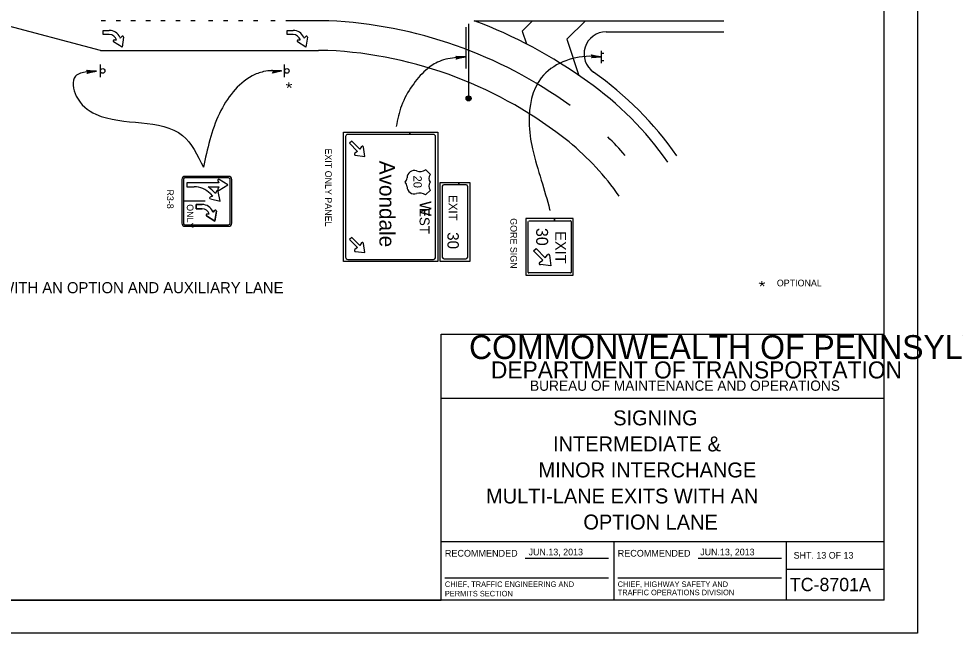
# Model space of a CAD drawing. Extents: x 644898 to 648326, y 298294 to 300670.
# Drawn here: x 645333.7 to 645756.3, y 298294.5 to 298571.8 of the extents above; entities that cross this region are included whole.
import ezdxf

# ---------------------------------------------------------------- set-up
doc = ezdxf.new("R2010")
doc.units = 0
for name, color, linetype in [('1', 7, 'Continuous'), ('2', 7, 'Continuous'), ('XCS-GRID-MIN', 7, 'Continuous')]:
    doc.layers.add(name, color=color, linetype=linetype)

msp = doc.modelspace()

# ---------------------------------------------------------------- linework, layer by layer
at = {"layer": '1'}
for p, q in [((645724.32, 298309.49), (645724.32, 298873.49)), ((645524.32, 298309.49), (645524.32, 298429.49)), ((645524.32, 298429.49), (645724.32, 298429.49)), ((645724.32, 298400.49), (645524.32, 298400.49)), ((645524.32, 298335.87), (645724.32, 298335.87)), ((645602.32, 298335.87), (645602.32, 298309.49)), ((645680.2, 298309.49), (645680.2, 298335.87)), ((645562.26, 298328.44), (645599.88, 298328.44)), ((645640.26, 298328.44), (645677.88, 298328.44)), ((645680.2, 298323.49), (645724.32, 298323.49)), ((645526.01, 298319.54), (645599.88, 298319.54)), ((645604.01, 298319.54), (645677.88, 298319.54)), ((645724.32, 298309.49), (644938.32, 298309.49)), ((644938.32, 298309.49), (645524.32, 298309.49))]:
    msp.add_line(p, q, dxfattribs=at)
at = {"layer": '2'}
for p, q in [((645370.54, 298557.51), (645319.78, 298570.89)), ((645372.84, 298570.89), (645370.84, 298570.89)), ((645379.59, 298570.89), (645377.59, 298570.89)), ((645386.34, 298570.89), (645384.34, 298570.89)), ((645393.09, 298570.89), (645391.09, 298570.89)), ((645399.84, 298570.89), (645397.84, 298570.89)), ((645406.59, 298570.89), (645404.59, 298570.89)), ((645413.34, 298570.89), (645411.34, 298570.89)), ((645421.34, 298570.89), (645419.34, 298570.89)), ((645428.09, 298570.89), (645426.09, 298570.89)), ((645434.84, 298570.89), (645432.84, 298570.89)), ((645441.59, 298570.89), (645439.59, 298570.89)), ((645449.45, 298570.89), (645447.45, 298570.89)), ((645473.61, 298570.89), (645454.2, 298570.89)), ((645539.18, 298570.89), (645598.81, 298570.89)), ((645565.62, 298570.89), (645560.93, 298566.2)), ((645589.44, 298570.89), (645581.09, 298562.54)), ((645598.81, 298570.89), (645651.96, 298570.89)), ((645535.6, 298549.4), (645535.6, 298567.99)), ((645536.72, 298569.47), (645536.72, 298535.78)), ((645560.93, 298566.2), (645562.85, 298560.41)), ((645598.81, 298565.89), (645651.96, 298565.89)), ((645581.09, 298562.54), (645586.5, 298546.22)), ((645370.54, 298557.51), (645442.59, 298557.51)), ((645442.59, 298557.51), (645454.2, 298557.51)), ((645454.2, 298557.51), (645468.92, 298557.51)), ((645596.63, 298551.75), (645596.63, 298557.38)), ((645596.63, 298556.25), (645597.75, 298556.25)), ((645370.54, 298545.44), (645370.54, 298551.07)), ((645453.63, 298545.44), (645453.63, 298551.07)), ((645596.63, 298552.88), (645597.75, 298552.88)), ((645537.22, 298536.53), (645535.97, 298536.16)), ((645536.1, 298536.53), (645537.22, 298536.53)), ((645537.22, 298535.03), (645536.6, 298536.78)), ((645536.6, 298536.78), (645537.72, 298535.66)), ((645537.72, 298535.66), (645537.22, 298536.66)), ((645537.47, 298536.03), (645535.85, 298535.66)), ((645536.6, 298535.03), (645535.85, 298535.91)), ((645535.85, 298535.91), (645537.22, 298535.03)), ((645535.85, 298535.66), (645537.72, 298535.66)), ((645535.97, 298536.16), (645537.47, 298536.03)), ((645537.72, 298535.66), (645535.97, 298535.28)), ((645535.97, 298535.28), (645537.47, 298535.28)), ((645537.47, 298535.28), (645536.6, 298535.03)), ((645536.72, 298535.78), (645536.72, 298535.78)), ((645480.21, 298462.22), (645480.21, 298520.6)), ((645480.21, 298520.6), (645510.23, 298520.6)), ((645510.23, 298519.6), (645510.23, 298520.6)), ((645510.23, 298520.6), (645522.83, 298520.6)), ((645510.23, 298520.6), (645510.23, 298519.6)), ((645522.83, 298520.6), (645522.83, 298462.22)), ((645481.21, 298518.6), (645481.21, 298464.22)), ((645483.94, 298516.57), (645482.94, 298515.57)), ((645482.94, 298515.57), (645486.56, 298511.95)), ((645487.56, 298512.89), (645483.94, 298516.57)), ((645521.83, 298464.22), (645521.83, 298518.6)), ((645486.56, 298511.95), (645485.37, 298511.07)), ((645488.37, 298514.07), (645487.56, 298512.89)), ((645489.81, 298509.7), (645489.31, 298513.82)), ((645485.56, 298510.2), (645489.81, 298509.7)), ((645517.21, 298503.76), (645519.46, 298501.51)), ((645423.55, 298498.77), (645423.94, 298497.79)), ((645428, 298496.85), (645424.21, 298499.31)), ((645508.96, 298500.01), (645508.96, 298500.01)), ((645423.94, 298497.79), (645409.55, 298497.79)), ((645409.55, 298497.79), (645409.55, 298495.95)), ((645409.55, 298495.95), (645412.85, 298495.95)), ((645419.14, 298495.92), (645423.94, 298495.92)), ((645422.42, 298492.96), (645421.35, 298494.1)), ((645423.94, 298495.92), (645423.55, 298494.94)), ((645424.21, 298494.39), (645428, 298496.85)), ((645508.96, 298496.01), (645508.96, 298496.01)), ((645511.46, 298495.76), (645511.46, 298495.76)), ((645513.71, 298498.01), (645513.71, 298498.01)), ((645513.71, 298498.01), (645513.71, 298498.01)), ((645513.71, 298498.01), (645513.71, 298498.01)), ((645513.71, 298498.01), (645513.71, 298498.01)), ((645513.71, 298498.01), (645513.71, 298498.01)), ((645513.71, 298498.01), (645513.71, 298498.01)), ((645519.46, 298494.38), (645517.21, 298492.26)), ((645523.83, 298462.22), (645523.83, 298497.85)), ((645523.83, 298497.85), (645532.29, 298497.85)), ((645524.83, 298496.22), (645524.83, 298464.1)), ((645532.29, 298496.85), (645525.58, 298496.85)), ((645532.29, 298496.85), (645532.29, 298497.85)), ((645532.29, 298497.85), (645537.33, 298497.85)), ((645532.29, 298497.85), (645532.29, 298496.85)), ((645535.58, 298496.85), (645532.29, 298496.85)), ((645536.33, 298464.1), (645536.33, 298496.22)), ((645537.33, 298497.85), (645537.33, 298462.22)), ((645420.04, 298492.86), (645421.11, 298491.72)), ((645421.11, 298491.72), (645420.1, 298491.32)), ((645420.16, 298490.47), (645424.55, 298489.4)), ((645422.88, 298493.95), (645422.42, 298492.96)), ((645424.55, 298489.4), (645423.73, 298493.85)), ((645512.21, 298492.76), (645512.21, 298492.76)), ((645575.53, 298481.6), (645562.57, 298481.6)), ((645562.57, 298481.6), (645562.57, 298456.08)), ((645575.53, 298480.6), (645575.53, 298481.6)), ((645583.95, 298481.6), (645575.53, 298481.6)), ((645575.53, 298481.6), (645575.53, 298480.6)), ((645583.95, 298456.08), (645583.95, 298481.6)), ((645563.57, 298457.33), (645563.57, 298480.35)), ((645563.82, 298480.6), (645575.53, 298480.6)), ((645575.53, 298480.6), (645582.7, 298480.6)), ((645582.95, 298480.35), (645582.95, 298457.33)), ((645483.94, 298473.12), (645482.94, 298472.12)), ((645487.56, 298469.43), (645483.94, 298473.12)), ((645482.94, 298472.12), (645486.56, 298468.5)), ((645488.37, 298470.62), (645487.56, 298469.43)), ((645489.81, 298466.25), (645489.31, 298470.37)), ((645486.56, 298468.5), (645485.37, 298467.62)), ((645485.56, 298466.75), (645489.81, 298466.25)), ((645566.01, 298467.06), (645567.14, 298468.06)), ((645570.26, 298462.81), (645566.01, 298467.06)), ((645567.14, 298468.06), (645571.26, 298463.94)), ((645571.26, 298463.94), (645572.26, 298465.31)), ((645573.26, 298465.06), (645573.89, 298460.31)), ((645522.83, 298462.22), (645480.21, 298462.22)), ((645482.21, 298463.22), (645520.83, 298463.22)), ((645537.33, 298462.22), (645523.83, 298462.22)), ((645525.58, 298463.47), (645535.58, 298463.47)), ((645568.76, 298461.81), (645570.26, 298462.81)), ((645573.89, 298460.31), (645569.14, 298460.94)), ((645562.57, 298456.08), (645583.95, 298456.08)), ((645582.7, 298457.08), (645563.82, 298457.08))]:
    msp.add_line(p, q, dxfattribs=at)
for points in [[(645374.57, 298564.61), (645371.85, 298564.61), (645371.85, 298566.49), (645374.57, 298566.49)], [(645457.56, 298564.61), (645454.84, 298564.61), (645454.84, 298566.49), (645457.56, 298566.49)], [(645380.96, 298563.46), (645380.34, 298558.99), (645376.5, 298561.38)], [(645376.72, 298562.21), (645377.78, 298562.27)], [(645379.35, 298563.41), (645379.49, 298563.09), (645380.19, 298563.83)], [(645463.95, 298563.46), (645463.32, 298558.99), (645459.49, 298561.38)], [(645459.7, 298562.21), (645460.77, 298562.27)], [(645462.33, 298563.41), (645462.48, 298563.09), (645463.18, 298563.83)], [(645531.16, 298554.7), (645531.29, 298554.58), (645535.29, 298554.58), (645531.16, 298554.7), (645530.91, 298554.95), (645535.29, 298554.58), (645531.41, 298554.08), (645531.29, 298553.83), (645535.29, 298554.58), (645531.16, 298553.58), (645531.29, 298553.83)], [(645592.33, 298555.19), (645592.44, 298555.06), (645596.42, 298554.58), (645592.33, 298555.19), (645592.12, 298555.47), (645596.42, 298554.58), (645592.51, 298554.54), (645592.35, 298554.31), (645596.42, 298554.58), (645592.2, 298554.08), (645592.35, 298554.31)], [(645364.6, 298548.26), (645364.73, 298548.14), (645368.73, 298548.14), (645364.6, 298548.26), (645364.35, 298548.51), (645368.73, 298548.14), (645364.85, 298547.64), (645364.73, 298547.39), (645368.73, 298548.14), (645364.6, 298547.14), (645364.73, 298547.39)], [(645448.2, 298548.37), (645448.33, 298548.25), (645452.33, 298548.25), (645448.2, 298548.37), (645447.95, 298548.62), (645452.33, 298548.25), (645448.45, 298547.75), (645448.33, 298547.5), (645452.33, 298548.25), (645448.2, 298547.25), (645448.33, 298547.5)], [(645510.23, 298519.6), (645482.21, 298519.6)], [(645520.83, 298519.6), (645510.23, 298519.6)], [(645407.3, 298499.25), (645407.3, 298479.56)], [(645408, 298499.25), (645408, 298479.56)], [(645428.39, 298500.65), (645408.71, 298500.65)], [(645428.39, 298499.95), (645408.71, 298499.95)], [(645423.55, 298498.77), (645423.94, 298497.79), (645409.55, 298497.79), (645409.55, 298495.95)], [(645424.21, 298494.39), (645428, 298496.85), (645424.21, 298499.31)], [(645429.1, 298479.56), (645429.1, 298499.25)], [(645429.8, 298479.56), (645429.8, 298499.25)], [(645409.55, 298495.95), (645412.85, 298495.95)], [(645419.14, 298495.92), (645423.94, 298495.92), (645423.55, 298494.94)], [(645422.88, 298493.95), (645422.42, 298492.96), (645421.35, 298494.1)], [(645420.04, 298492.86), (645421.11, 298491.72), (645420.1, 298491.32)], [(645420.16, 298490.47), (645424.55, 298489.4), (645423.73, 298493.85)], [(645417.8, 298489.4), (645408, 298489.4)], [(645416.48, 298486.08), (645413.76, 298486.08), (645413.76, 298487.95), (645416.48, 298487.95)], [(645413.76, 298487.95), (645413.76, 298486.08), (645416.48, 298486.08)], [(645416.48, 298487.95), (645413.76, 298487.95)], [(645422.87, 298484.92), (645422.25, 298480.45), (645418.42, 298482.85)], [(645418.42, 298482.85), (645422.25, 298480.45), (645422.87, 298484.92)], [(645418.63, 298483.67), (645419.69, 298483.74)], [(645419.69, 298483.74), (645418.63, 298483.67)], [(645421.26, 298484.88), (645421.4, 298484.56), (645422.1, 298485.29)], [(645422.1, 298485.29), (645421.4, 298484.56), (645421.26, 298484.88)], [(645408.71, 298478.86), (645428.39, 298478.86)], [(645408.71, 298478.15), (645428.39, 298478.15)]]:
    msp.add_lwpolyline(points, dxfattribs=at)
for centre, radius in [((645371.58, 298548.25), 1.03), ((645454.67, 298548.25), 1.03), ((645536.71, 298535.85), 1.12)]:
    msp.add_circle(centre, radius, dxfattribs=at)
for centre, radius, start, end in [((645463.66, 298368.33), 202.81, 54.115, 87.1891), ((645463.66, 298368.33), 216.18, 54.1362, 69.554), ((645374.57, 298561.24), 5.25, 24.5121, 90), ((645457.56, 298561.24), 5.25, 24.5121, 90), ((645598.81, 298555.89), 10, 90, 234.8419), ((645374.57, 298561.24), 3.38, 17.8867, 90), ((645376.74, 298561.76), 0.448, 93.3962, 237.975), ((645380.52, 298563.52), 0.448, 352.025, 136.6038), ((645457.56, 298561.24), 3.38, 17.8867, 90), ((645459.73, 298561.76), 0.448, 93.3962, 237.975), ((645463.51, 298563.52), 0.448, 352.025, 136.6038), ((645471.38, 297956.21), 601.31, 89.8236, 90.23471), ((645463.66, 298368.33), 189.43, 51.3209, 87.1047), ((645504.05, 298421.35), 154.56, 34.9711, 54.8419), ((645504.05, 298421.35), 149.56, 34.9711, 54.7736), ((645482.21, 298518.6), 1, 90, 180), ((645520.83, 298518.6), 1, 360, 90), ((645504.05, 298421.35), 122.81, 34.9711, 50.5694), ((645504.05, 298421.35), 136.19, 40.6935, 45.5167), ((645485.66, 298510.66), 0.489, 123.2449, 267.1516), ((645488.81, 298513.77), 0.489, 4.8565, 145.522), ((645512.2, 298500.01), 3.26, 71.452, 179.9953), ((645514.65, 298507.42), 4.55, 251.8289, 304.5747), ((645408.71, 298499.25), 1.41, 90, 180), ((645408.71, 298499.25), 0.703, 90, 180), ((645423.97, 298498.94), 0.448, 57.025, 201.6038), ((645423.97, 298498.94), 0.448, 57.025, 201.6038), ((645428.39, 298499.25), 1.41, 360, 90), ((645428.39, 298499.25), 0.703, 360, 90), ((645506.18, 298500.01), 2.76, 313.7275, 0), ((645521.75, 298499.76), 2.93, 143.136, 216.864), ((645412.85, 298486.05), 9.9, 43.4316, 90), ((645412.85, 298486.05), 9.9, 43.4316, 90), ((645412.85, 298486.05), 11.7, 43.4316, 57.4528), ((645412.85, 298486.05), 11.7, 43.4316, 57.4528), ((645423.29, 298493.77), 0.448, 10.4566, 155.0355), ((645423.29, 298493.77), 0.448, 10.4566, 155.0355), ((645423.97, 298494.77), 0.448, 158.3962, 302.975), ((645423.97, 298494.77), 0.448, 158.3962, 302.975), ((645506.18, 298495.99), 2.76, 0, 46.2725), ((645512.2, 298496), 3.26, 180.0047, 288.548), ((645521.75, 298496.25), 2.93, 143.136, 216.864), ((645420.26, 298490.9), 0.448, 111.8278, 256.4066), ((645420.26, 298490.9), 0.448, 111.8278, 256.4066), ((645514.65, 298488.58), 4.55, 55.4253, 108.1711), ((645416.48, 298482.7), 5.25, 24.5121, 90), ((645416.48, 298482.7), 5.25, 24.5121, 90), ((645416.48, 298482.7), 3.38, 17.8867, 90), ((645416.48, 298482.7), 3.38, 17.8867, 90), ((645418.65, 298483.23), 0.448, 93.3962, 237.975), ((645418.65, 298483.23), 0.448, 93.3962, 237.975), ((645422.43, 298484.99), 0.448, 352.025, 136.6038), ((645422.43, 298484.99), 0.448, 352.025, 136.6038), ((645408.71, 298479.56), 1.41, 180, 270), ((645408.71, 298479.56), 0.703, 180, 270), ((645428.39, 298479.56), 1.41, 270, 360), ((645428.39, 298479.56), 0.703, 270, 360), ((645582.7, 298480.35), 0.25, 360, 90), ((645488.81, 298470.32), 0.489, 4.8565, 145.522), ((645485.66, 298467.21), 0.489, 123.2449, 267.1516), ((645572.72, 298464.94), 0.559, 4.8591, 145.5247), ((645482.21, 298464.22), 1, 180, 270), ((645520.83, 298464.22), 1, 270, 0), ((645569.12, 298461.38), 0.559, 123.2476, 267.1542), ((645563.82, 298457.33), 0.25, 180, 270)]:
    msp.add_arc(centre, radius, start, end, dxfattribs=at)
for centre, major_axis, ratio, start_param, end_param in [((645525.63, 298496.17), (-0.792, 0), 0.827467, 4.712389, 6.283185), ((645535.48, 298496.17), (-0.792, 0), 0.827467, 3.141593, 4.712389), ((645525.63, 298464.14), (0.792, 0), 0.827467, 3.141593, 4.712389), ((645535.48, 298464.14), (0.792, 0), 0.827467, 4.712389, 6.283185), ((645582.7, 298457.33), (0.25, 0), 0.999585, 4.712389, 6.283185)]:
    msp.add_ellipse(centre, major_axis=major_axis, ratio=ratio, start_param=start_param, end_param=end_param, dxfattribs=at)
for points in [[(645535.29, 298554.58), (645530.41, 298554.2), (645522.61, 298552.16), (645517.38, 298548.57), (645511.28, 298541.53), (645506.44, 298532.51), (645504.04, 298523.18)], [(645596.04, 298554.61), (645591.21, 298554.83), (645569.53, 298545.16), (645564.02, 298525.14), (645565.57, 298513.04), (645569.53, 298498.96), (645573.27, 298485.76), (645573.38, 298485.32)], [(645366.64, 298547.97), (645364.4, 298547.8), (645359.29, 298545.85), (645359.67, 298536.88), (645368.51, 298528.67), (645407.6, 298519.1), (645417.02, 298504.74)], [(645452.33, 298548.25), (645444.15, 298547.91), (645439.04, 298545.96), (645424.28, 298529.05), (645417.02, 298504.74)]]:
    msp.add_spline(points, degree=3, dxfattribs=at)
at = {"layer": 'XCS-GRID-MIN'}
msp.add_lwpolyline([(644898.32, 298888.49), (645739.32, 298888.49), (645739.32, 298294.49), (644898.32, 298294.49)], close=True, dxfattribs=at)

# ---------------------------------------------------------------- texts
at = {"layer": '1'}
for s, height, p in [('COMMONWEALTH OF PENNSYLVANIA', 10.7828, (645536.92, 298418.23)), ('DEPARTMENT OF TRANSPORTATION', 7.6837, (645546.78, 298409.48)), ('BUREAU OF MAINTENANCE AND OPERATIONS', 4.6253, (645564.42, 298403.91)), ('SIGNING', 6.75, (645601.97, 298388.31)), ('INTERMEDIATE & ', 6.75, (645574.82, 298376.56)), ('MINOR INTERCHANGE', 6.75, (645568.25, 298364.81)), ('MULTI-LANE EXITS WITH AN', 6.75, (645544.6, 298353.06)), ('OPTION LANE', 6.75, (645588.5, 298341.31)), ('RECOMMENDED', 3.048, (645526.01, 298329.07)), ('RECOMMENDED', 3.048, (645604.01, 298329.07)), ('SHT. 13 OF 13', 3, (645683.41, 298328.18)), ('CHIEF, TRAFFIC ENGINEERING AND', 2.5, (645526.01, 298315.38)), ('CHIEF, HIGHWAY SAFETY AND', 2.5, (645604.01, 298315.38)), ('TC-8701A', 6, (645681.69, 298313.49)), ('PERMITS SECTION', 2.5, (645526.01, 298311.13)), ('TRAFFIC OPERATIONS DIVISION', 2.5, (645604.01, 298311.68))]:
    msp.add_text(s, height=height, dxfattribs=at).set_placement(p)
at = {"layer": '2'}
for s, height, rotation, p in [('*', 5.42, 75.7789, (645459.19, 298539.4)), ('EXIT ONLY PANEL', 3, 270, (645471.95, 298513.26)), ('Avondale', 7, 269.9998, (645496.46, 298507.72)), ('20', 3.75, 270, (645511.83, 298501.01)), ('R3-8', 3, 270, (645400.56, 298494.75)), ('EXIT', 3.875, 270, (645527.73, 298492.2)), ('ONLY', 3, 270, (645409.55, 298488.1)), ('EST', 4.5, 270, (645514.58, 298486.38)), ('W', 5.38, 270, (645514.58, 298489.51)), ('GORE SIGN', 3, 270, (645555.58, 298481.77)), ('30', 5.125, 270, (645527.16, 298475.48)), ('30', 5.375, 270, (645567.21, 298477.37)), ('EXIT', 4.917, 270, (645575.81, 298475.9)), ('*', 5.42, 75.7789, (645672.65, 298449.84))]:
    msp.add_text(s, height=height, rotation=rotation, dxfattribs=at).set_placement(p)
for s, height, p in [('INTERMEDIATE & MINOR INTERCHANGE MULTI-LANE EXITS WITH AN OPTION AND AUXILIARY LANE', 5, (645129.96, 298447.94)), ('OPTIONAL', 3, (645675.82, 298451.05)), ('JUN.13, 2013', 3, (645563.79, 298329.65)), ('JUN.13, 2013', 3, (645641.24, 298329.65))]:
    msp.add_text(s, height=height, dxfattribs=at).set_placement(p)

doc.saveas('drawing.dxf')
